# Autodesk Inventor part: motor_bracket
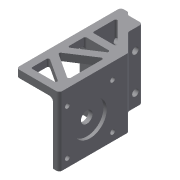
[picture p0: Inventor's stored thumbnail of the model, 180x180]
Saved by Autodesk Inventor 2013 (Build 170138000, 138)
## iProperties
Created: 2013-11
Part Number: motor_bracket
Material: Generic
Document SubType Name: Modeling
Designer: Jonas
Density: 1 g/cm^3
Author: Jonas
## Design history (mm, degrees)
sketch "Sketch1"
  geometry: L1 (5, -42.3)-(0, -42.3); L2 (0, -42.3)-(0, 0); L3 (-24.5, 0)-(-24.5, 29.5); L4 (-24.5, 29.5)-(-19.5, 29.5); L5 (-19.5, 29.5)-(5, 5); L6 (-24.5, 0)-(0, 0); L7 (5, 5)-(5, -42.3); L8 (-19.5, 22.429)-(-2.071, 5); L9 (-2.071, 5)-(-19.5, 5); L10 (-19.5, 5)-(-19.5, 22.429)
  constraints: 20 end point, 3 perpendicular, 2 horizontal, 2 parallel, 2 point on line, 2 vertical
  dimensions: "d23" = 42.3 distance of L1.end L2.end; "d24" = 45 deg angle of L6 L5; "d28" = 5 distance of L3.end L4.end (= d30); "d29" = 47.3 distance of L5.end L1.start (= d23 + d30); "d30" = 5 distance of L1.start L1.end; "d31" = 29.5 distance from line of L3.start L7 (computed from d30); "d32" = 5 distance between parallel lines of L6 L9 (= d30); "d33" = 5 distance between parallel lines of L3 L10 (= d30); "d34" = 5 distance between parallel lines of L5 L8 (= d30)
extrude "Extrusion1" new body sketch "Sketch1" distance "d0" = 42.3 (= d23); taper "d1" = 0 deg
sketch "Sketch7"
  geometry: L1 (0, 42.3)-(0, 0) reference; L2 (0, 0)-(42.3, 0) reference; L3 (42.3, 42.3)-(42.3, 0) reference; L4 (0, 42.3)-(42.3, 42.3) reference; L5 (21.15, 42.3)-(21.15, 0); L6 (21.15, 21.15)-(42.3, 21.15); L7 (21.15, 21.15)-(0, 21.15); C1 r 4 at (21.15, 21.15); C2 r 1.6 at (5.65, 36.65); C3 r 1.6 at (36.65, 36.65); C4 r 1.6 at (36.65, 5.65); C5 r 1.6 at (5.65, 5.65); 3 further points
  constraints: 6 end point, 5 centre point, 5 midpoint, 3 coincident, 10 other
  dimensions: "d35" = 8 diameter of C1; "d36" = 3.2 diameter of C2; "d37" = 15.5 horizontal distance of C2.centre C1.centre; "d38" = 15.5 horizontal distance of C2.centre L6.start (= d37); "d41" = 360 deg dimension on L6.start C2.centre (derived)
extrude "Extrusion6" cut sketch "Sketch7" stored distance "d43" = 0; taper "d44" = 0 deg
sketch "Sketch9"
  geometry: C1 r 4 at (-21.15, 21.15) reference; C2 r 11.5 at (-21.15, 21.15); 1 further point
  constraints: 1 centre point, 1 coincident
  dimensions: "d45" = 23 diameter of C2
extrude "Extrusion7" cut sketch "Sketch9" distance "d46" = 2.2; taper "d47" = 0 deg
sketch "Sketch10"
  geometry: L1 (-2.071, 5)-(-19.5, 5) reference; L2 (-19.5, 5)-(-19.5, 22.429) reference; L3 (-19.5, 22.429)-(-2.071, 5) reference; L4 (0, 0)-(0, -42.3) reference; L5 (0, -42.3)-(5, -42.3) reference; L6 (5, -42.3)-(5, 5) reference; L7 (5, 5)-(-19.5, 29.5) reference; L8 (-19.5, 29.5)-(-24.5, 29.5) reference; L9 (-24.5, 29.5)-(-24.5, 0) reference; L10 (-24.5, 0)-(0, 0) reference
extrude "Extrusion8" join sketch "Sketch10" distance "d48" = 5; taper "d49" = 0 deg
sketch "Sketch12"
  geometry: L1 (0, 0)-(47.3, 0) reference; L2 (47.3, 42.3)-(42.3, 42.3); L3 (42.3, 42.3)-(42.3, 0); L4 (42.3, 0)-(47.3, 0); L5 (47.3, 0)-(47.3, 42.3)
  constraints: 8 end point, 2 parallel, 1 horizontal, 1 perpendicular, 1 point on line
  dimensions: "d53" = 5 distance of L4.end L3.end
extrude "Extrusion10" join sketch "Sketch12" stored distance "d54" = 5; taper "d55" = 0 deg
sketch "Sketch15"
  geometry: L1 (5, -42.3)-(-24.5, -42.3) reference; L2 (5, -42.3)-(5, 5) reference; L3 (-24.5, 29.5)-(-24.5, -42.3) reference; L4 (-19.5, 0)-(0, 0); L5 (0, 0)-(-19.5, -12.685); L6 (-19.5, -12.685)-(-19.5, 0); L7 (-19.5, -18.65)-(0, -5.965); L8 (0, -31.335)-(-19.5, -18.65); L9 (-19.5, -24.615)-(0, -37.3); L10 (0, -37.3)-(-19.5, -37.3); L11 (-19.5, -37.3)-(-19.5, -24.615); L12 (0, -31.335)-(0, -5.965); L13 (0, 0)-(-24.5, 0) reference
  constraints: 18 end point, 5 point on line, 3 perpendicular, 2 parallel, 1 collinear, 1 vertical
  dimensions: "d56" = 5 distance between parallel lines of L3 L6; "d57" = 5 distance between parallel lines of L1 L10 (= d56); "d59" = 5 distance between parallel lines of L2 L12 (= d56); "d60" = 5 distance between parallel lines of L7 L5 (= d56); "d61" = 5 distance between parallel lines of L8 L9 (= d56)
extrude "Extrusion11" cut sketch "Sketch15" stored distance "d62" = 5; taper "d63" = 0 deg
sketch "Sketch17"
  geometry: L1 (5, 5)-(-19.5, 29.5) reference; L2 (-19.5, 29.5)-(-24.5, 29.5) reference; L3 (-24.5, 29.5)-(-24.5, -42.3) reference; L4 (-17.5, 27.5)-(-7.5, 27.5); L5 (-7.5, 27.5)-(-7.5, 17.5)
  constraints: 4 end point, 2 perpendicular, 2 point on line
  dimensions: "d68" = 2 distance between parallel lines of L2 L4; "d69" = 10 distance of L4.end L5.end
extrude "Extrusion13" join sketch "Sketch17" stored distance "d70" = 5; taper "d71" = 0 deg
sketch "Sketch18"
  geometry: L1 (47.3, 10)-(47.3, 0) reference; L2 (0, 10)-(47.3, 10) reference; L3 (0, 0)-(0, 10) reference; L4 (47.3, 5)-(0, 5); L5 (23.65, 5)-(23.65, 10); C1 r 1.6 at (41.65, -23.15) reference; C2 r 1.6 at (10.65, -23.15) reference; 3 further points
  constraints: 4 end point, 4 midpoint, 2 point on line
  dimensions: "d82" = 3 horizontal distance of C1.centre point (38.65, 5); "d83" = 3 horizontal distance of C2.centre point (13.65, 5) (= d82)
hole "Hole2" sketch "Sketch18" at (38.65, 5), (13.65, 5) diameter "d72" = 4.5; stored, may be unused: countersink angle "d76" = 90 deg, drill point angle "d78" = 118 deg; dims "d73" = 6, "d74" = 4, "d75" = 2, "d77" = 8
fillet "Fillet1" dims "d79" = 1
fillet "Fillet2" dims "d80" = 1
fillet "Fillet3" dims "d81" = 2
body "Solid1"
other parameters: "d25" = 6
